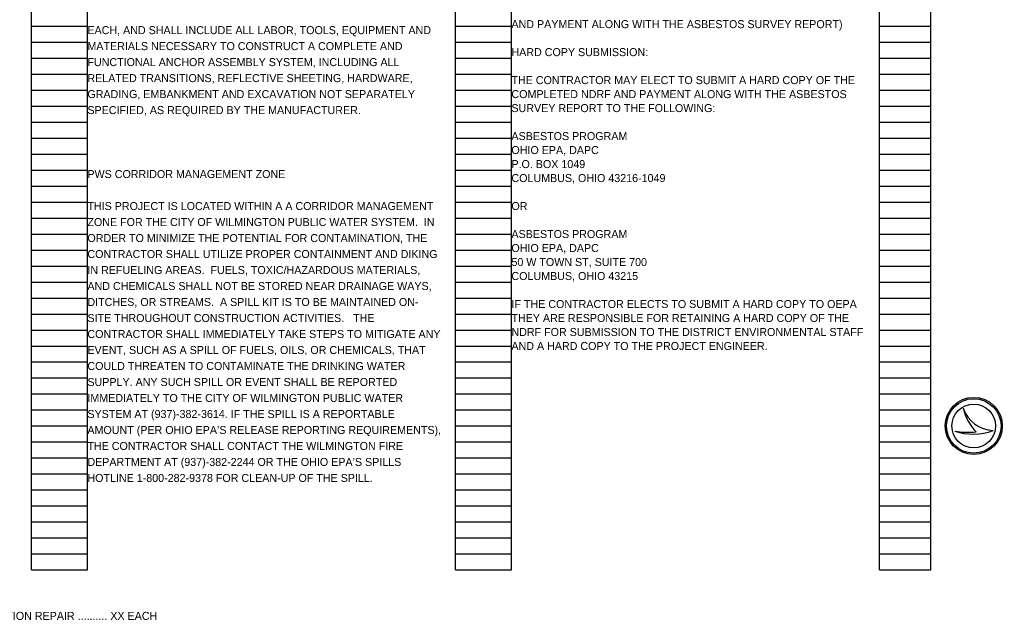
# Model space of a CAD drawing. Extents: x 0 to 78.9, y -24.2 to 22.
# Drawn here: x 61.36 to 78.55, y -0.49 to 10.04 of the extents above; entities that cross this region are included whole.
import ezdxf

# ---------------------------------------------------------------- set-up
doc = ezdxf.new("R2010")
doc.units = 0
doc.layers.add('SH_Data', color=7, linetype='Continuous')
doc.layers.add('SH_Text', color=7, linetype='Continuous')

msp = doc.modelspace()

# ---------------------------------------------------------------- linework, layer by layer
at = {"layer": 'SH_Data'}
for p, q in [((61.561, 0.407), (61.561, 20.567)), ((62.541, 0.407), (62.541, 20.567)), ((68.981, 0.407), (68.981, 20.567)), ((69.961, 0.407), (69.961, 20.567)), ((76.401, 0.407), (76.401, 20.567)), ((77.301, 0.407), (77.301, 20.567)), ((61.561, 9.927), (62.541, 9.927)), ((68.981, 9.927), (69.961, 9.927)), ((76.401, 9.927), (77.301, 9.927)), ((61.561, 9.647), (62.541, 9.647)), ((68.981, 9.647), (69.961, 9.647)), ((76.401, 9.647), (77.301, 9.647)), ((61.561, 9.367), (62.541, 9.367)), ((68.981, 9.367), (69.961, 9.367)), ((76.401, 9.367), (77.301, 9.367)), ((61.561, 9.087), (62.541, 9.087)), ((68.981, 9.087), (69.961, 9.087)), ((76.401, 9.087), (77.301, 9.087)), ((61.561, 8.807), (62.541, 8.807)), ((68.981, 8.807), (69.961, 8.807)), ((76.401, 8.807), (77.301, 8.807)), ((61.561, 8.527), (62.541, 8.527)), ((68.981, 8.527), (69.961, 8.527)), ((76.401, 8.527), (77.301, 8.527)), ((61.561, 8.247), (62.541, 8.247)), ((68.981, 8.247), (69.961, 8.247)), ((76.401, 8.247), (77.301, 8.247)), ((61.561, 7.967), (62.541, 7.967)), ((68.981, 7.967), (69.961, 7.967)), ((76.401, 7.967), (77.301, 7.967)), ((61.561, 7.687), (62.541, 7.687)), ((68.981, 7.687), (69.961, 7.687)), ((76.401, 7.687), (77.301, 7.687)), ((61.561, 7.407), (62.541, 7.407)), ((68.981, 7.407), (69.961, 7.407)), ((76.401, 7.407), (77.301, 7.407)), ((61.561, 7.127), (62.541, 7.127)), ((68.981, 7.127), (69.961, 7.127)), ((76.401, 7.127), (77.301, 7.127)), ((61.561, 6.847), (62.541, 6.847)), ((68.981, 6.847), (69.961, 6.847)), ((76.401, 6.847), (77.301, 6.847)), ((61.561, 6.567), (62.541, 6.567)), ((68.981, 6.567), (69.961, 6.567)), ((76.401, 6.567), (77.301, 6.567)), ((61.561, 6.287), (62.541, 6.287)), ((68.981, 6.287), (69.961, 6.287)), ((76.401, 6.287), (77.301, 6.287)), ((61.561, 6.007), (62.541, 6.007)), ((68.981, 6.007), (69.961, 6.007)), ((76.401, 6.007), (77.301, 6.007)), ((61.561, 5.727), (62.541, 5.727)), ((68.981, 5.727), (69.961, 5.727)), ((76.401, 5.727), (77.301, 5.727)), ((61.561, 5.447), (62.541, 5.447)), ((68.981, 5.447), (69.961, 5.447)), ((76.401, 5.447), (77.301, 5.447)), ((61.561, 5.167), (62.541, 5.167)), ((68.981, 5.167), (69.961, 5.167)), ((76.401, 5.167), (77.301, 5.167)), ((61.561, 4.887), (62.541, 4.887)), ((68.981, 4.887), (69.961, 4.887)), ((76.401, 4.887), (77.301, 4.887)), ((61.561, 4.607), (62.541, 4.607)), ((68.981, 4.607), (69.961, 4.607)), ((76.401, 4.607), (77.301, 4.607)), ((61.561, 4.327), (62.541, 4.327)), ((68.981, 4.327), (69.961, 4.327)), ((76.401, 4.327), (77.301, 4.327)), ((61.561, 4.047), (62.541, 4.047)), ((68.981, 4.047), (69.961, 4.047)), ((76.401, 4.047), (77.301, 4.047)), ((61.561, 3.767), (62.541, 3.767)), ((68.981, 3.767), (69.961, 3.767)), ((76.401, 3.767), (77.301, 3.767)), ((61.561, 3.487), (62.541, 3.487)), ((68.981, 3.487), (69.961, 3.487)), ((76.401, 3.487), (77.301, 3.487)), ((61.561, 3.207), (62.541, 3.207)), ((68.981, 3.207), (69.961, 3.207)), ((76.401, 3.207), (77.301, 3.207)), ((77.869, 3.237), (77.869, 3.237)), ((61.561, 2.927), (62.541, 2.927)), ((68.981, 2.927), (69.961, 2.927)), ((76.401, 2.927), (77.301, 2.927)), ((77.718, 2.837), (77.718, 2.837)), ((78.389, 2.846), (78.389, 2.846)), ((61.561, 2.647), (62.541, 2.647)), ((68.981, 2.647), (69.961, 2.647)), ((76.401, 2.647), (77.301, 2.647)), ((61.561, 2.367), (62.541, 2.367)), ((68.981, 2.367), (69.961, 2.367)), ((76.401, 2.367), (77.301, 2.367)), ((61.561, 2.087), (62.541, 2.087)), ((68.981, 2.087), (69.961, 2.087)), ((76.401, 2.087), (77.301, 2.087)), ((61.561, 1.807), (62.541, 1.807)), ((68.981, 1.807), (69.961, 1.807)), ((76.401, 1.807), (77.301, 1.807)), ((61.561, 1.527), (62.541, 1.527)), ((68.981, 1.527), (69.961, 1.527)), ((76.401, 1.527), (77.301, 1.527)), ((61.561, 1.247), (62.541, 1.247)), ((68.981, 1.247), (69.961, 1.247)), ((76.401, 1.247), (77.301, 1.247)), ((61.561, 0.967), (62.541, 0.967)), ((68.981, 0.967), (69.961, 0.967)), ((76.401, 0.967), (77.301, 0.967)), ((61.561, 0.687), (62.541, 0.687)), ((68.981, 0.687), (69.961, 0.687)), ((76.401, 0.687), (77.301, 0.687)), ((61.561, 0.407), (62.541, 0.407)), ((68.981, 0.407), (69.961, 0.407)), ((76.401, 0.407), (77.301, 0.407))]:
    msp.add_line(p, q, dxfattribs=at)
for radius in [0.5, 0.477, 0.477, 0.382]:
    msp.add_circle((78.051, 2.927), radius, dxfattribs=at)
for centre, radius, start, end in [((78.417, 3.425), 0.58, 198.9257, 198.9319), ((78.648, 3.397), 0.796, 191.6379, 191.6421), ((78.417, 3.425), 0.58, 198.9319, 267.1657), ((78.648, 3.397), 0.796, 191.6421, 226.0947), ((77.949, 4.082), 1.266, 259.4964, 259.4995), ((78.041, 3.797), 1.013, 251.4527, 251.4576), ((78.041, 3.797), 1.013, 251.4576, 290.0832), ((77.949, 4.082), 1.266, 259.4995, 276.6672)]:
    msp.add_arc(centre, radius, start, end, dxfattribs=at)

# ---------------------------------------------------------------- texts
at = {"layer": 'SH_Text'}
for s, p in [('AND PAYMENT ALONG WITH THE ASBESTOS SURVEY REPORT)', (69.961, 9.892)), ('EACH, AND SHALL INCLUDE ALL LABOR, TOOLS, EQUIPMENT AND', (62.541, 9.787)), ('MATERIALS NECESSARY TO CONSTRUCT A COMPLETE AND', (62.541, 9.507)), ('HARD COPY SUBMISSION:', (69.961, 9.402)), ('FUNCTIONAL ANCHOR ASSEMBLY SYSTEM, INCLUDING ALL', (62.541, 9.227)), ('RELATED TRANSITIONS, REFLECTIVE SHEETING, HARDWARE,', (62.541, 8.947)), ('THE CONTRACTOR MAY ELECT TO SUBMIT A HARD COPY OF THE ', (69.961, 8.912)), ('GRADING, EMBANKMENT AND EXCAVATION NOT SEPARATELY', (62.541, 8.667)), ('COMPLETED NDRF AND PAYMENT ALONG WITH THE ASBESTOS ', (69.961, 8.667)), ('SPECIFIED, AS REQUIRED BY THE MANUFACTURER.', (62.541, 8.387)), ('SURVEY REPORT TO THE FOLLOWING:', (69.961, 8.422)), ('ASBESTOS PROGRAM', (69.961, 7.932)), ('OHIO EPA, DAPC', (69.961, 7.687)), ('P.O. BOX 1049', (69.961, 7.442)), ('PWS CORRIDOR MANAGEMENT ZONE', (62.541, 7.267)), ('COLUMBUS, OHIO 43216-1049', (69.961, 7.197)), ('THIS PROJECT IS LOCATED WITHIN A A CORRIDOR MANAGEMENT ', (62.541, 6.707)), ('OR ', (69.961, 6.707)), ('ZONE FOR THE CITY OF WILMINGTON PUBLIC WATER SYSTEM.\xa0 IN ', (62.541, 6.427)), ('ORDER TO MINIMIZE THE POTENTIAL FOR CONTAMINATION, THE ', (62.541, 6.147)), ('ASBESTOS PROGRAM ', (69.961, 6.217)), ('OHIO EPA, DAPC ', (69.961, 5.972)), ('CONTRACTOR SHALL UTILIZE PROPER CONTAINMENT AND DIKING ', (62.541, 5.867)), ('50 W TOWN ST, SUITE 700', (69.961, 5.727)), ('IN REFUELING AREAS.\xa0 FUELS, TOXIC/HAZARDOUS MATERIALS, ', (62.541, 5.587)), ('COLUMBUS, OHIO 43215', (69.961, 5.482)), ('AND CHEMICALS SHALL NOT BE STORED NEAR DRAINAGE WAYS, ', (62.541, 5.307)), ('DITCHES, OR STREAMS.\xa0 A SPILL KIT IS TO BE MAINTAINED ON-', (62.541, 5.027)), ('IF THE CONTRACTOR ELECTS TO SUBMIT A HARD COPY TO OEPA ', (69.961, 4.992)), ('SITE THROUGHOUT CONSTRUCTION ACTIVITIES.\xa0\xa0 THE ', (62.541, 4.747)), ('THEY ARE RESPONSIBLE FOR RETAINING A HARD COPY OF THE ', (69.961, 4.747)), ('NDRF FOR SUBMISSION TO THE DISTRICT ENVIRONMENTAL STAFF ', (69.961, 4.502)), ('CONTRACTOR SHALL IMMEDIATELY TAKE STEPS TO MITIGATE ANY ', (62.541, 4.467)), ('EVENT, SUCH AS A SPILL OF FUELS, OILS, OR CHEMICALS, THAT ', (62.541, 4.187)), ('AND A HARD COPY TO THE PROJECT ENGINEER.', (69.961, 4.257)), ('COULD THREATEN TO CONTAMINATE THE DRINKING WATER ', (62.541, 3.907)), ('SUPPLY. ANY SUCH SPILL OR EVENT SHALL BE REPORTED ', (62.541, 3.627)), ('IMMEDIATELY TO THE CITY OF WILMINGTON PUBLIC WATER ', (62.541, 3.347)), ('SYSTEM AT (937)-382-3614. IF THE SPILL IS A REPORTABLE ', (62.541, 3.067)), ('AMOUNT (PER OHIO EPA’S RELEASE REPORTING REQUIREMENTS), ', (62.541, 2.787)), ('THE CONTRACTOR SHALL CONTACT THE WILMINGTON FIRE ', (62.541, 2.507)), ('DEPARTMENT AT (937)-382-2244 OR THE OHIO EPA’S SPILLS ', (62.541, 2.227)), ('HOTLINE 1-800-282-9378 FOR CLEAN-UP OF THE SPILL.\xa0 ', (62.541, 1.947)), ('- ITEM 514, FINAL INSPECTION REPAIR .......... XX EACH', (58.812, -0.468))]:
    msp.add_text(s, height=0.14, dxfattribs=at).set_placement(p)

doc.saveas('drawing.dxf')
